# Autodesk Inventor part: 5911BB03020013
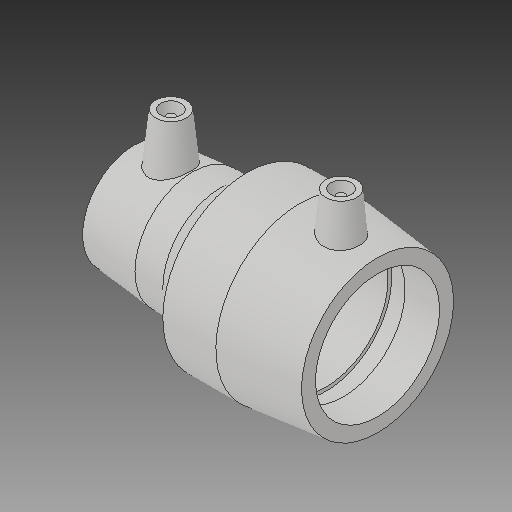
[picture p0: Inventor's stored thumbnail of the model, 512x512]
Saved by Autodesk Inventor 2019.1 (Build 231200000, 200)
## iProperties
Created: 2017-06
Part Number: 5911BB03020013
Material: Generic
Description: PLASSON ASTM REDUCING COUPLER 2''IPS-1 1/4''IPS
Document SubType Name: Modeling
Designer: KIM
Mass: 54.8237 g
Surface Area: 155.252 cm^2
Volume: 54.8237 cm^3
Density: 1 g/cm^3
Appearance: Default
Author: KIM
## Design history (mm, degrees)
derived "5911.ipt"
feature "Solid1::5911.ipt"
tag "TaggingFeature1"
body "Solid1"
other parameters: "d0" = 117.856, "d2" = 55.88, "d3" = 46.99, "d4" = 28.194, "d5" = 50.292, "d7" = 42.1, "d8" = 168 deg, "d10" = 18.796, "d11" = 6.26533, "d14" = 17.6296, "d22" = 108.92847, "d29" = 49.022, "d30" = 15, "d31" = 41.2496, "d34" = 6 deg, "d41" = 4, "d42" = 14, "d43" = 0, "d48" = 55.88, "d49" = 60.1, "d50" = 81.788, "d52" = 37.89, "d53" = 24.9936, "d54" = 8.3312, "d55" = 168 deg, "d56" = 37.4904, "d57" = 62.484, "d58" = 73.6092, "d59" = 2.3495, "d60" = 135 deg, "d61" = 56.896, "d62" = 15, "d64" = 4, "d66" = 5 deg, "d67" = 14, "d68" = 0, "d69" = 41.2496, "d95" = 3, "d96" = 0, "d97" = 3, "d98" = 0, "d_1" = 42.1, "L_" = 117.856, "L_2" = 46.99, "D_1" = 55.88, "A_1" = 49.022, "d_2" = 12, "L_1" = 62.484, "d_" = 60.1, "A_" = 56.896, "D_" = 81.788
